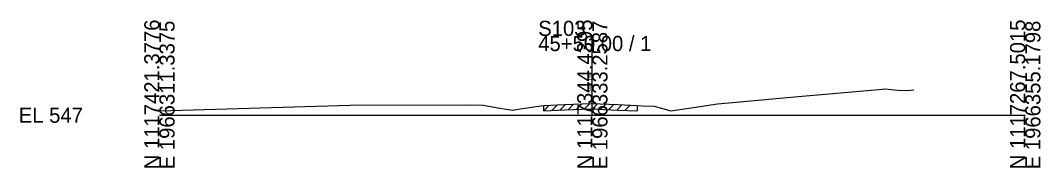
# Model space of a CAD drawing. Extents: x -26 to 163, y -10 to 45020.
# Drawn here: x -25.7 to 162.8, y 5490.3 to 5517.5 of the extents above; entities that cross this region are included whole.
import ezdxf

# ---------------------------------------------------------------- set-up
doc = ezdxf.new("R2010")
doc.units = 0
for name, color, linetype in [('RD_GPK_XS_Cell', 7, 'Continuous'), ('RD_XS_ExGround', 7, 'Continuous'), ('RD_XS_ExPaveRet', 7, 'Continuous'), ('RD_XS_TX_Elev_EX', 7, 'Continuous')]:
    doc.layers.add(name, color=color, linetype=linetype)

msp = doc.modelspace()

# ---------------------------------------------------------------- linework, layer by layer
at = {"layer": 'RD_GPK_XS_Cell'}
for p, q in [((80, 5500), (80, 5514.66)), ((0, 5500), (80, 5500)), ((80, 5500), (160, 5500))]:
    msp.add_line(p, q, dxfattribs=at)
at = {"layer": 'RD_XS_ExGround'}
for p, q in [((106.58, 5502.41), (118.06, 5503.44)), ((118.06, 5503.44), (132.96, 5504.73)), ((132.96, 5504.73), (133.58, 5504.79)), ((133.58, 5504.79), (134.09, 5504.89)), ((134.09, 5504.89), (136.37, 5504.65)), ((136.37, 5504.65), (138.31, 5504.57)), ((138.31, 5504.57), (139.41, 5504.68)), ((0, 5500.78), (35.23, 5501.86)), ((35.23, 5501.86), (56.33, 5501.94)), ((56.33, 5501.94), (59.84, 5501.84)), ((59.84, 5501.84), (62.88, 5501.32)), ((67.5, 5501.33), (69.61, 5501.61)), ((69.61, 5501.61), (71.01, 5501.81)), ((71.01, 5501.81), (74.85, 5501.97)), ((74.85, 5501.97), (79.8, 5502.17)), ((79.8, 5502.17), (84.72, 5501.95)), ((84.72, 5501.95), (88.23, 5501.8)), ((88.23, 5501.8), (89.2, 5501.76)), ((89.2, 5501.76), (91.4, 5501.65)), ((91.4, 5501.65), (93.2, 5501.15)), ((94.42, 5500.82), (98.68, 5501.41)), ((98.68, 5501.41), (103.11, 5502.1)), ((103.11, 5502.1), (106.58, 5502.41)), ((62.88, 5501.32), (65.33, 5500.93)), ((65.33, 5500.93), (66.27, 5501.09)), ((66.27, 5501.09), (67.5, 5501.33)), ((93.2, 5501.15), (94.42, 5500.82))]:
    msp.add_line(p, q, dxfattribs=at)
at = {"layer": 'RD_XS_ExPaveRet'}
for p, q in [((71.01, 5500.81), (72.05, 5501.86)), ((71.01, 5500.81), (71.01, 5501.81)), ((72.51, 5500.87), (73.55, 5501.92)), ((74.01, 5500.93), (75.05, 5501.98)), ((75.51, 5501), (76.55, 5502.04)), ((77.01, 5501.06), (78.05, 5502.1)), ((78.51, 5501.12), (79.55, 5502.16)), ((80.01, 5501.16), (80.97, 5502.12)), ((81.51, 5501.09), (82.47, 5502.05)), ((83.01, 5501.02), (83.97, 5501.98)), ((84.51, 5500.96), (85.47, 5501.91)), ((86.01, 5500.89), (86.97, 5501.85)), ((88.27, 5501.8), (88.27, 5500.8)), ((71.01, 5500.81), (74.85, 5500.97)), ((74.85, 5500.97), (79.8, 5501.17)), ((79.8, 5501.17), (84.72, 5500.95)), ((84.72, 5500.95), (88.23, 5500.8)), ((88.23, 5500.8), (88.27, 5500.8))]:
    msp.add_line(p, q, dxfattribs=at)

# ---------------------------------------------------------------- texts
at = {"layer": 'RD_GPK_XS_Cell'}
for s, p in [('N 1117421.3776', (0, 5490)), ('E 1966311.3375', (2.8, 5490)), ('N 1117344.4395', (80, 5490)), ('E 1966333.2587', (82.8, 5490)), ('N 1117267.5015', (160, 5490)), ('E 1966355.1798', (162.8, 5490))]:
    msp.add_text(s, height=2.8, rotation=90, dxfattribs=at).set_placement(p)
for s, p in [('S103', (70, 5514.66)), ('45+50.00 / 1', (70, 5511.86)), ('EL 547', (-26, 5498.6))]:
    msp.add_text(s, height=2.8, dxfattribs=at).set_placement(p)
at = {"layer": 'RD_XS_TX_Elev_EX'}
msp.add_text('549.16', height=0.8, rotation=90, dxfattribs=at).set_placement((79.9, 5504.16))

doc.saveas('drawing.dxf')
